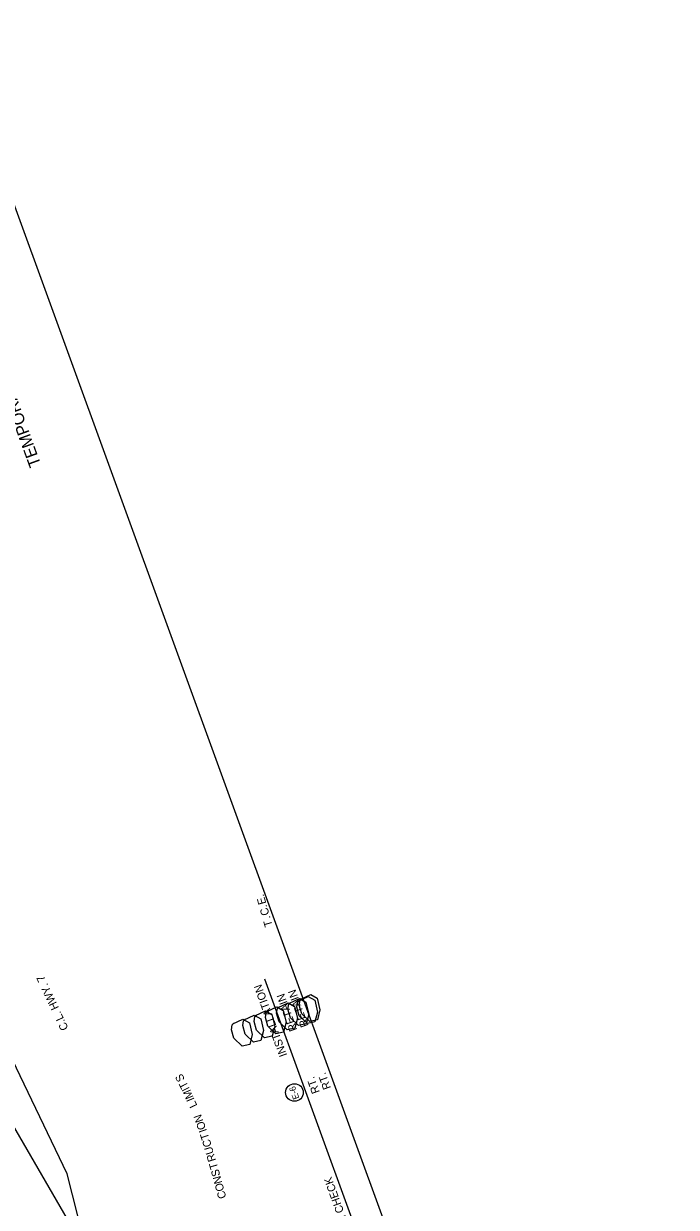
# Model space of a CAD drawing. Extents: x 960650 to 962115, y 1906901 to 1908757.
# Drawn here: x 961626 to 962115, y 1907870 to 1908757 of the extents above; entities that cross this region are included whole.
import ezdxf

# ---------------------------------------------------------------- set-up
doc = ezdxf.new("R2010")
doc.units = 0
for name, color, linetype in [('1', 7, 'Continuous'), ('44', 7, 'Continuous'), ('60', 7, 'Continuous'), ('NO PLOT', 7, 'Continuous'), ('R_Draft', 7, 'Continuous'), ('S_TREE', 7, 'Continuous')]:
    doc.layers.add(name, color=color, linetype=linetype)

msp = doc.modelspace()

# ---------------------------------------------------------------- linework, layer by layer
at = {"layer": '1'}
msp.add_circle((961828.42, 1907955.76), 6.61, dxfattribs=at)
at = {"layer": '44'}
msp.add_line((961888.65, 1907814.33), (961806.22, 1908040.8), dxfattribs=at)
at = {"layer": 'NO PLOT'}
msp.add_lwpolyline([(962114.55, 1907257.7), (961568.91, 1908756.85), (961079.18, 1908578.6), (961182.12, 1908295.76), (961245.55, 1908318.85), (961390.91, 1907919.48), (961327.48, 1907896.39), (961425.36, 1907627.47), (961483.4, 1907648.6), (961600.59, 1907326.6), (961542.56, 1907305.48), (961624.82, 1907079.46)], close=True, dxfattribs=at)
msp.add_lwpolyline([(962114.55, 1907257.7), (961568.91, 1908756.85), (961079.18, 1908578.6), (961182.12, 1908295.76), (961245.55, 1908318.85), (961390.91, 1907919.48), (961327.48, 1907896.39), (961425.36, 1907627.47), (961483.4, 1907648.6), (961600.59, 1907326.6), (961542.56, 1907305.48), (961624.82, 1907079.46)], close=True, dxfattribs=at)
msp.add_lwpolyline([(962114.55, 1907257.7), (961568.91, 1908756.85), (961079.18, 1908578.6), (961182.12, 1908295.76), (961245.55, 1908318.85), (961390.91, 1907919.48), (961327.48, 1907896.39), (961425.36, 1907627.47), (961483.4, 1907648.6), (961600.59, 1907326.6), (961542.56, 1907305.48), (961624.82, 1907079.46)], close=True, dxfattribs=at)
msp.add_lwpolyline([(962114.55, 1907257.7), (961568.91, 1908756.85), (961079.18, 1908578.6), (961182.12, 1908295.76), (961245.55, 1908318.85), (961390.91, 1907919.48), (961327.48, 1907896.39), (961425.36, 1907627.47), (961483.4, 1907648.6), (961600.59, 1907326.6), (961542.56, 1907305.48), (961624.82, 1907079.46)], close=True, dxfattribs=at)
msp.add_lwpolyline([(961666.04, 1907863.2), (961658.05, 1907894.81), (961540.67, 1908139.08), (961533.72, 1908140.56), (961533.72, 1908140.56), (961533.71, 1908140.68), (961532.94, 1908142.63), (961447.22, 1908293.28), (961348.44, 1908423.3), (961301.2, 1908468.29), (961296.15, 1908480.78), (961212.84, 1908631.51), (961200.57, 1908627.76), (961278, 1908455.78), (961347.64, 1908371.59), (961398.93, 1908274.74), (961531.16, 1908140.88), (961533.72, 1908140.56), (961533.72, 1908140.56), (961540.75, 1908123.08), (961535.28, 1908075.65), (961546.11, 1908053.77), (961660.88, 1907856.14)], dxfattribs=at)
at = {"layer": 'S_TREE'}
for points in [[(961816.18, 1908019.53), (961823.65, 1908023.01), (961828.48, 1908020.28), (961830.63, 1908011.45), (961828.7, 1908004.07), (961822.99, 1908002.8), (961816.91, 1908008.68), (961815.06, 1908015.13), (961815.67, 1908018.78), (961816.86, 1908020)], [(961824.64, 1908022.6), (961832.11, 1908026.09), (961836.94, 1908023.36), (961839.09, 1908014.53), (961837.15, 1908007.15), (961831.45, 1908005.87), (961825.37, 1908011.76), (961823.51, 1908018.2), (961824.13, 1908021.86), (961825.32, 1908023.08)], [(961824.64, 1908022.6), (961832.11, 1908026.09), (961836.94, 1908023.36), (961839.09, 1908014.53), (961837.15, 1908007.15), (961831.45, 1908005.87), (961825.37, 1908011.76), (961823.51, 1908018.2), (961824.13, 1908021.86), (961825.32, 1908023.08)], [(961831.29, 1908024.11), (961838.76, 1908027.59), (961843.59, 1908024.86), (961845.74, 1908016.03), (961843.8, 1908008.65), (961838.1, 1908007.38), (961832.02, 1908013.26), (961830.16, 1908019.71), (961830.78, 1908023.36), (961831.97, 1908024.58)], [(961833.1, 1908025.68), (961840.57, 1908029.17), (961845.4, 1908026.43), (961847.55, 1908017.61), (961845.61, 1908010.22), (961839.91, 1908008.95), (961833.83, 1908014.84), (961831.97, 1908021.28), (961832.58, 1908024.94), (961833.78, 1908026.16)], [(961790.81, 1908010.29), (961798.28, 1908013.78), (961803.11, 1908011.04), (961805.26, 1908002.22), (961803.33, 1907994.83), (961797.62, 1907993.56), (961791.54, 1907999.45), (961789.69, 1908005.89), (961790.3, 1908009.55), (961791.49, 1908010.77)], [(961790.81, 1908010.29), (961798.28, 1908013.78), (961803.11, 1908011.04), (961805.26, 1908002.22), (961803.33, 1907994.83), (961797.62, 1907993.56), (961791.54, 1907999.45), (961789.69, 1908005.89), (961790.3, 1908009.55), (961791.49, 1908010.77)], [(961790.81, 1908010.29), (961798.28, 1908013.78), (961803.11, 1908011.04), (961805.26, 1908002.22), (961803.33, 1907994.83), (961797.62, 1907993.56), (961791.54, 1907999.45), (961789.69, 1908005.89), (961790.3, 1908009.55), (961791.49, 1908010.77)], [(961799.27, 1908013.37), (961806.74, 1908016.85), (961811.57, 1908014.12), (961813.72, 1908005.29), (961811.78, 1907997.91), (961806.08, 1907996.64), (961800, 1908002.52), (961798.14, 1908008.97), (961798.75, 1908012.62), (961799.95, 1908013.84)], [(961799.27, 1908013.37), (961806.74, 1908016.85), (961811.57, 1908014.12), (961813.72, 1908005.29), (961811.78, 1907997.91), (961806.08, 1907996.64), (961800, 1908002.52), (961798.14, 1908008.97), (961798.75, 1908012.62), (961799.95, 1908013.84)], [(961799.27, 1908013.37), (961806.74, 1908016.85), (961811.57, 1908014.12), (961813.72, 1908005.29), (961811.78, 1907997.91), (961806.08, 1907996.64), (961800, 1908002.52), (961798.14, 1908008.97), (961798.75, 1908012.62), (961799.95, 1908013.84)], [(961799.27, 1908013.37), (961806.74, 1908016.85), (961811.57, 1908014.12), (961813.72, 1908005.29), (961811.78, 1907997.91), (961806.08, 1907996.64), (961800, 1908002.52), (961798.14, 1908008.97), (961798.75, 1908012.62), (961799.95, 1908013.84)], [(961799.27, 1908013.37), (961806.74, 1908016.85), (961811.57, 1908014.12), (961813.72, 1908005.29), (961811.78, 1907997.91), (961806.08, 1907996.64), (961800, 1908002.52), (961798.14, 1908008.97), (961798.75, 1908012.62), (961799.95, 1908013.84)], [(961807.72, 1908016.45), (961815.2, 1908019.93), (961820.03, 1908017.2), (961822.18, 1908008.37), (961820.24, 1908000.99), (961814.54, 1907999.72), (961808.46, 1908005.6), (961806.6, 1908012.05), (961807.21, 1908015.7), (961808.41, 1908016.92)], [(961807.72, 1908016.45), (961815.2, 1908019.93), (961820.03, 1908017.2), (961822.18, 1908008.37), (961820.24, 1908000.99), (961814.54, 1907999.72), (961808.46, 1908005.6), (961806.6, 1908012.05), (961807.21, 1908015.7), (961808.41, 1908016.92)], [(961807.72, 1908016.45), (961815.2, 1908019.93), (961820.03, 1908017.2), (961822.18, 1908008.37), (961820.24, 1908000.99), (961814.54, 1907999.72), (961808.46, 1908005.6), (961806.6, 1908012.05), (961807.21, 1908015.7), (961808.41, 1908016.92)], [(961807.72, 1908016.45), (961815.2, 1908019.93), (961820.03, 1908017.2), (961822.18, 1908008.37), (961820.24, 1908000.99), (961814.54, 1907999.72), (961808.46, 1908005.6), (961806.6, 1908012.05), (961807.21, 1908015.7), (961808.41, 1908016.92)], [(961807.72, 1908016.45), (961815.2, 1908019.93), (961820.03, 1908017.2), (961822.18, 1908008.37), (961820.24, 1908000.99), (961814.54, 1907999.72), (961808.46, 1908005.6), (961806.6, 1908012.05), (961807.21, 1908015.7), (961808.41, 1908016.92)], [(961782.35, 1908007.21), (961789.82, 1908010.7), (961794.65, 1908007.96), (961796.8, 1907999.14), (961794.87, 1907991.76), (961789.16, 1907990.48), (961783.09, 1907996.37), (961781.23, 1908002.81), (961781.84, 1908006.47), (961783.03, 1908007.69)]]:
    msp.add_lwpolyline(points, dxfattribs=at)

# ---------------------------------------------------------------- texts
at = {"layer": '1'}
msp.add_text('E-6 ', height=4.8, rotation=110, dxfattribs=at).set_placement((961832.16, 1907951.58))
at = {"layer": '44'}
for s, p in [('INSTALLATION', (961823, 1907983.73)), ('RETAIN', (961839.08, 1908005.88)), ('RETAIN', (961830.62, 1908002.8)), ('RT.', (961855.89, 1907959.22)), ('RT.', (961847.43, 1907956.14)), ('ROCK DITCH CHECK', (961883.48, 1907817.55))]:
    msp.add_text(s, height=6, rotation=110, dxfattribs=at).set_placement(p)
at = {"layer": '60'}
msp.add_text('TEMPORARY EROSION CONTROL DETAILS', height=9, rotation=110, dxfattribs=at).set_placement((961638.71, 1908426.37))
at = {"layer": 'R_Draft'}
for s, rotation, p in [('E', 105.85702, (961807.38, 1908097.54)), ('.', 105.85702, (961805.9, 1908102.72)), ('C', 105.85702, (961809.73, 1908089.27)), ('.', 105.85702, (961808.18, 1908094.73)), ('T', 105.85702, (961812.13, 1908080.82)), ('.', 105.85702, (961810.53, 1908086.45)), ('C.L. HWY. 7', 115.13979, (961659.2, 1908003.88)), ('S', 117.15524, (961746.47, 1907965.61)), ('T', 117.15524, (961749.14, 1907960.4)), ('I', 116.84755, (961750.04, 1907958.6)), ('M', 112.84289, (961752.83, 1907952.35)), ('I', 112.84289, (961753.6, 1907950.52)), ('L', 115.68492, (961755.8, 1907945.93)), ('N', 109.99434, (961760.25, 1907934.5)), ('O', 109.05137, (961762.24, 1907928.88)), ('I', 109.05137, (961762.89, 1907927.01)), ('T', 108.15514, (961764.78, 1907921.37)), ('C', 105.94998, (961766.5, 1907915.72)), ('U', 106.46963, (961768.09, 1907910.24)), ('R', 107.0037, (961769.72, 1907904.87)), ('T', 106.37635, (961771.37, 1907899.18)), ('S', 105.3414, (961772.91, 1907893.61)), ('N', 105.25856, (961774.4, 1907888.13)), ('O', 105.26485, (961775.95, 1907882.48)), ('C', 105.43073, (961777.45, 1907877.03))]:
    msp.add_text(s, height=6, rotation=rotation, dxfattribs=at).set_placement(p)

doc.saveas('drawing.dxf')
